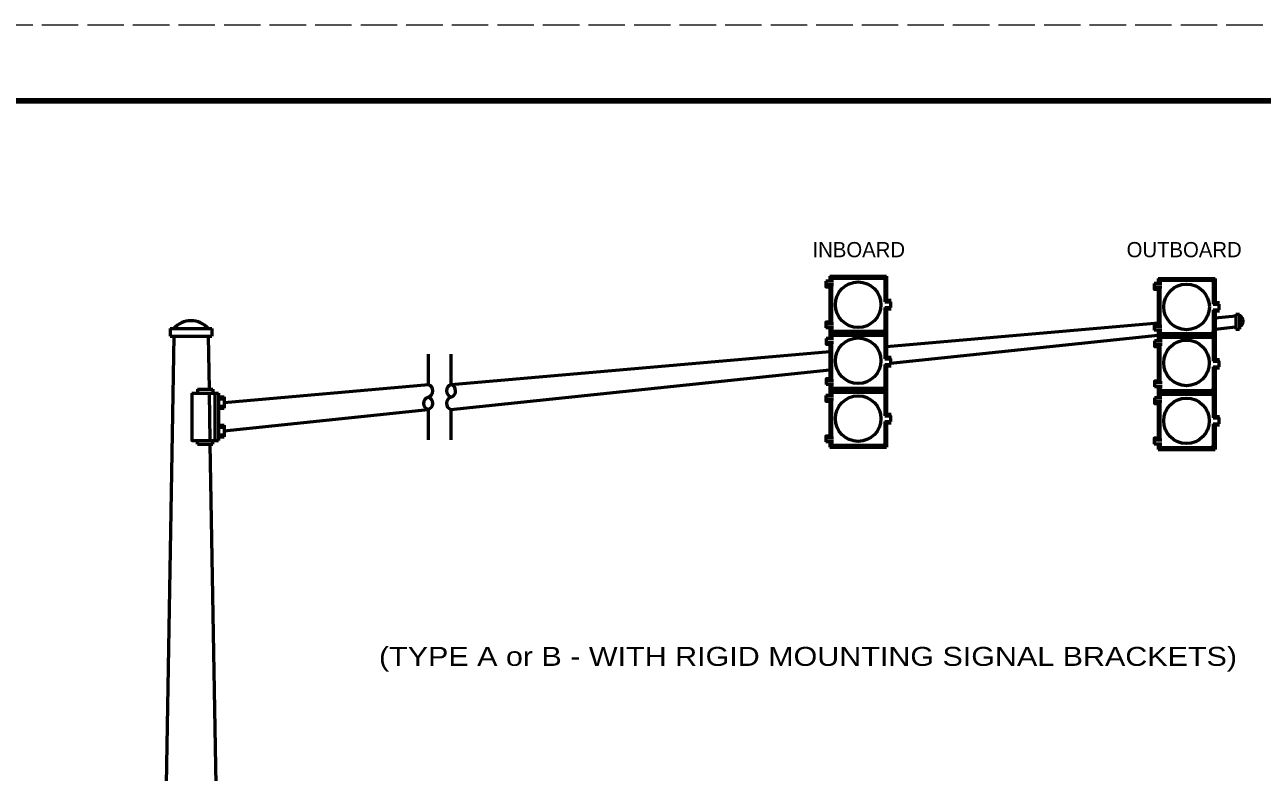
# Model space of a CAD drawing. Extents: x -286 to 394, y -156 to 284.
# Drawn here: x -36.6 to 126.4, y 186.1 to 284.5 of the extents above; entities that cross this region are included whole.
import ezdxf
from ezdxf.enums import TextEntityAlignment as Align

# ---------------------------------------------------------------- set-up
doc = ezdxf.new("R2010")
doc.units = 0
doc.header["$LTSCALE"] = 0.8
doc.linetypes.add('LONG_DASHED', pattern=[7.5, 6, -1.5])
doc.layers.add('1', color=7, linetype='Continuous', lineweight=53)
doc.layers.add('61', color=7, linetype='Continuous', lineweight=35)

msp = doc.modelspace()

# ---------------------------------------------------------------- linework, layer by layer
at = {"layer": '1'}
for p, q in [((69.4161, 251.3764), (76.9161, 251.3764)), ((69.4161, 251.3764), (69.4161, 250.7164)), ((69.9161, 251.1264), (76.4161, 251.1264)), ((76.9161, 251.3764), (76.9161, 248.0014)), ((112.6687, 251.0868), (120.1687, 251.0868)), ((112.6687, 251.0868), (112.6687, 250.4268)), ((120.1687, 251.0868), (120.1687, 247.7118)), ((69.9161, 250.7164), (68.9161, 250.7164)), ((69.9161, 250.2164), (68.9161, 250.2164)), ((69.4161, 250.2164), (69.4161, 245.056)), ((69.6661, 250.8764), (69.6661, 250.7164)), ((69.6661, 250.2164), (69.6661, 245.056)), ((76.6661, 250.8764), (76.6661, 248.0014)), ((113.1687, 250.4268), (112.1687, 250.4268)), ((113.1687, 249.9268), (112.1687, 249.9268)), ((112.6687, 249.9268), (112.6687, 244.7664)), ((112.9187, 250.5868), (112.9187, 250.4268)), ((112.9187, 249.9268), (112.9187, 244.7664)), ((113.1687, 250.8368), (119.6687, 250.8368)), ((119.9187, 250.5868), (119.9187, 247.7118)), ((76.6661, 248.0014), (77.4161, 248.0014)), ((77.2911, 248.3764), (77.2911, 248.0014)), ((77.4161, 248.0014), (77.4161, 247.2514)), ((120.5437, 248.0868), (120.5437, 247.7118)), ((76.6661, 247.2514), (76.6661, 244.3764)), ((76.6661, 247.2514), (77.4161, 247.2514)), ((76.9161, 247.2514), (76.9161, 240.5014)), ((77.2911, 247.2514), (77.2911, 246.8764)), ((119.9187, 247.7118), (120.6687, 247.7118)), ((119.9187, 246.9618), (119.9187, 244.0868)), ((119.9187, 246.9618), (120.6687, 246.9618)), ((120.1687, 246.9618), (120.1687, 240.2118)), ((120.1687, 245.9052), (122.9091, 246.1449)), ((120.5437, 246.9618), (120.5437, 246.5868)), ((120.6687, 247.7118), (120.6687, 246.9618)), ((122.9097, 246.3725), (122.9041, 244.4116)), ((122.9097, 246.3725), (123.4097, 246.3711)), ((123.4097, 246.3711), (123.4041, 244.4102)), ((-17.4518, 244.4995), (-11.9517, 244.4995)), ((-17.4518, 244.4995), (-17.4518, 243.4995)), ((-11.9517, 244.4995), (-11.9517, 243.4995)), ((69.9161, 245.056), (68.9161, 245.056)), ((69.9161, 244.556), (68.9161, 244.556)), ((69.4161, 244.556), (69.4161, 243.1619)), ((69.6661, 244.556), (69.6661, 244.3764)), ((76.9161, 242.1211), (112.6687, 245.249)), ((113.1687, 244.7664), (112.1687, 244.7664)), ((120.1687, 244.4009), (122.9049, 244.6885)), ((-16.9518, 243.4995), (-18.8017, 137.5157)), ((-17.4518, 243.4995), (-11.9517, 243.4995)), ((-12.4518, 243.4995), (-12.3297, 236.5006)), ((69.9369, 243.1619), (68.9369, 243.1619)), ((69.4161, 243.8764), (76.9161, 243.8764)), ((69.6661, 243.3764), (69.6661, 243.1619)), ((69.9161, 244.1264), (76.4161, 244.1264)), ((69.9161, 243.6264), (76.4161, 243.6264)), ((76.6661, 243.3764), (76.6661, 240.5014)), ((77.4161, 239.9077), (112.6687, 243.6128)), ((113.1687, 244.2664), (112.1687, 244.2664)), ((113.1895, 242.8723), (112.1895, 242.8723)), ((112.6687, 244.2664), (112.6687, 242.8723)), ((112.6687, 243.5868), (120.1687, 243.5868)), ((112.9187, 244.2664), (112.9187, 244.0868)), ((112.9187, 243.0868), (112.9187, 242.8723)), ((113.1687, 243.8368), (119.6687, 243.8368)), ((113.1687, 243.3368), (119.6687, 243.3368)), ((119.9187, 243.0868), (119.9187, 240.2118)), ((122.9041, 244.4117), (123.4041, 244.4102)), ((19.5676, 237.1037), (69.4161, 241.4649)), ((69.9369, 242.6619), (68.9369, 242.6619)), ((69.4161, 242.6619), (69.4161, 237.6124)), ((69.6661, 242.6619), (69.6661, 237.6124)), ((113.1895, 242.3723), (112.1895, 242.3723)), ((112.6687, 242.3723), (112.6687, 237.3228)), ((112.9187, 242.3723), (112.9187, 237.3228)), ((16.5676, 237.1037), (16.5676, 241.1037)), ((19.5676, 237.1037), (19.5676, 241.1037)), ((76.6661, 239.7514), (77.4161, 239.7514)), ((76.6661, 239.7514), (76.6661, 236.8764)), ((76.9161, 239.7514), (76.9161, 233.0014)), ((77.2911, 240.8764), (77.2911, 240.5014)), ((77.2911, 239.7514), (77.2911, 239.3764)), ((120.5437, 240.5868), (120.5437, 240.2118)), ((19.5224, 233.8228), (69.4161, 239.0667)), ((119.9187, 239.4618), (120.6687, 239.4618)), ((119.9187, 239.4618), (119.9187, 236.5868)), ((120.1687, 239.4618), (120.1687, 232.7118)), ((120.5437, 239.4618), (120.5437, 239.0868)), ((-13.8297, 236.5006), (-11.8297, 236.5006)), ((-13.8297, 236.5006), (-13.8297, 236.0006)), ((-11.8297, 236.5006), (-11.8297, 236.0006)), ((-10.3297, 234.7506), (16.5676, 237.1037)), ((69.9369, 237.6124), (68.9369, 237.6124)), ((69.9369, 237.1124), (68.9369, 237.1124)), ((69.4161, 237.1124), (69.4161, 235.6753)), ((69.4161, 236.3764), (76.9161, 236.3764)), ((69.6661, 237.1124), (69.6661, 236.8764)), ((69.9161, 236.6264), (76.4161, 236.6264)), ((113.1895, 237.3228), (112.1895, 237.3228)), ((113.1895, 236.8228), (112.1895, 236.8228)), ((112.6687, 236.8228), (112.6687, 235.3857)), ((112.9187, 236.8228), (112.9187, 236.5868)), ((113.1687, 236.3368), (119.6687, 236.3368)), ((-14.5797, 236.0006), (-11.0797, 236.0006)), ((-12.3209, 236.0006), (-12.2118, 229.7506)), ((-11.5797, 236.0006), (-11.5797, 229.7506)), ((-11.0797, 236.0006), (-11.0797, 229.7506)), ((-11.0797, 235.5006), (-10.3297, 235.5006)), ((-11.0797, 235.2506), (-10.3297, 235.2506)), ((-10.3297, 235.5006), (-10.3297, 234.0006)), ((69.9286, 235.6753), (68.9286, 235.6753)), ((69.9286, 235.1753), (68.9286, 235.1753)), ((69.4161, 235.1753), (69.4161, 230.0765)), ((69.6661, 235.8764), (69.6661, 235.6753)), ((69.6661, 235.1753), (69.6661, 230.0765)), ((69.9161, 236.1264), (76.4161, 236.1264)), ((76.6661, 235.8764), (76.6661, 233.0014)), ((113.1812, 235.3857), (112.1812, 235.3857)), ((113.1812, 234.8857), (112.1812, 234.8857)), ((112.6687, 236.0868), (120.1687, 236.0868)), ((112.6687, 234.8857), (112.6687, 229.7869)), ((112.9187, 235.5868), (112.9187, 235.3857)), ((112.9187, 234.8857), (112.9187, 229.7869)), ((113.1687, 235.8368), (119.6687, 235.8368)), ((119.9187, 235.5868), (119.9187, 232.7118)), ((-11.0797, 234.2506), (-10.3297, 234.2506)), ((-11.0797, 234.0006), (-10.3297, 234.0006)), ((-10.3297, 231.0006), (16.5224, 233.8228)), ((16.5224, 233.8228), (16.5224, 229.8228)), ((19.5224, 233.8228), (19.5224, 229.8228)), ((77.2911, 233.3764), (77.2911, 233.0014)), ((120.5437, 233.0868), (120.5437, 232.7118)), ((-11.0797, 231.7506), (-10.3297, 231.7506)), ((-11.0797, 231.5006), (-10.3297, 231.5006)), ((-10.3297, 231.7506), (-10.3297, 230.2506)), ((76.6661, 232.2514), (77.4161, 232.2514)), ((76.6661, 232.2514), (76.6661, 229.3764)), ((76.9161, 232.2514), (76.9161, 228.8764)), ((77.2911, 232.2514), (77.2911, 231.8764)), ((119.9187, 231.9618), (120.6687, 231.9618)), ((119.9187, 231.9618), (119.9187, 229.0868)), ((120.1687, 231.9618), (120.1687, 228.5868)), ((120.5437, 231.9618), (120.5437, 231.5868)), ((-11.0797, 230.5006), (-10.3297, 230.5006)), ((-11.0797, 230.2506), (-10.3297, 230.2506)), ((69.9154, 230.0765), (68.9154, 230.0765)), ((-13.8297, 229.2506), (-13.8297, 229.7506)), ((-13.8297, 229.2506), (-11.8297, 229.2506)), ((-12.2031, 229.2506), (-10.6018, 137.5157)), ((-11.8297, 229.2506), (-11.8297, 229.7506)), ((69.9154, 229.5765), (68.9154, 229.5765)), ((69.4161, 229.5765), (69.4161, 228.8764)), ((69.4161, 228.8764), (76.9161, 228.8764)), ((69.6661, 229.5765), (69.6661, 229.3764)), ((69.9161, 229.1264), (76.4161, 229.1264)), ((113.168, 229.7869), (112.168, 229.7869)), ((113.168, 229.2869), (112.168, 229.2869)), ((112.6687, 229.2869), (112.6687, 228.5868)), ((112.6687, 228.5868), (120.1687, 228.5868)), ((112.9187, 229.2869), (112.9187, 229.0868)), ((113.1687, 228.8368), (119.6687, 228.8368))]:
    msp.add_line(p, q, dxfattribs=at)
for points in [[(68.9161, 250.7164), (68.9161, 249.9664), (69.4161, 249.9664)], [(112.1687, 250.4268), (112.1687, 249.6768), (112.6687, 249.6768)], [(69.4161, 245.306), (68.9161, 245.306), (68.9161, 244.556)], [(112.6687, 245.0164), (112.1687, 245.0164), (112.1687, 244.2664)], [(68.9369, 243.1619), (68.9369, 242.4119), (69.4161, 242.4119)], [(112.1895, 242.8723), (112.1895, 242.1223), (112.6687, 242.1223)], [(76.6661, 240.5014), (77.4161, 240.5014), (77.4161, 239.7514)], [(119.9187, 240.2118), (120.6687, 240.2118), (120.6687, 239.4618)], [(69.4369, 237.8624), (68.9369, 237.8624), (68.9369, 237.1124)], [(112.6895, 237.5728), (112.1895, 237.5728), (112.1895, 236.8228)], [(-14.5797, 236.0006), (-14.5797, 229.7506), (-11.0797, 229.7506)], [(68.9286, 235.6753), (68.9286, 234.9253), (69.4286, 234.9253)], [(112.1812, 235.3857), (112.1812, 234.6357), (112.6812, 234.6357)], [(76.6661, 233.0014), (77.4161, 233.0014), (77.4161, 232.2514)], [(119.9187, 232.7118), (120.6687, 232.7118), (120.6687, 231.9618)], [(69.4154, 230.3265), (68.9154, 230.3265), (68.9154, 229.5765)], [(112.668, 230.0369), (112.168, 230.0369), (112.168, 229.2869)]]:
    msp.add_lwpolyline(points, dxfattribs=at)
for centre in [(73.1692, 247.6235), (116.4218, 247.3339), (73.1635, 240.2517), (116.4161, 239.9621), (73.1633, 232.6276), (116.4159, 232.338)]:
    msp.add_circle(centre, 3, dxfattribs=at)
for centre, radius, start, end in [((69.9161, 250.8765), 0.25, 90, 180), ((76.4161, 250.8765), 0.25, 0, 90), ((113.1687, 250.5869), 0.25, 90, 180), ((119.6687, 250.5869), 0.25, 0, 90), ((123.059, 245.4659), 0.8032, 295.52475, 64.15201), ((-14.7017, 242.4682), 3.0312, 42.07502, 137.92498), ((69.9161, 244.3765), 0.25, 180, 270), ((69.9161, 243.3765), 0.25, 90, 180), ((76.4161, 244.3765), 0.25, 270, 0), ((76.4161, 243.3765), 0.25, 0, 90), ((113.1687, 244.0869), 0.25, 180, 270), ((113.1687, 243.0869), 0.25, 90, 180), ((119.6687, 244.0869), 0.25, 270, 0), ((119.6687, 243.0869), 0.25, 0, 90), ((16.2948, 236.2871), 0.861, 286.89464, 71.52798), ((19.8178, 236.28), 0.861, 106.89464, 251.52798), ((19.2955, 236.28), 0.861, 288.47202, 73.10536), ((69.9161, 236.8765), 0.25, 180, 270), ((76.4161, 236.8765), 0.25, 270, 0), ((113.1687, 236.5869), 0.25, 180, 270), ((119.6687, 236.5869), 0.25, 270, 0), ((16.7945, 234.6466), 0.861, 108.47202, 253.10536), ((16.2722, 234.6466), 0.861, 286.89464, 71.52798), ((19.7952, 234.6395), 0.861, 106.89464, 251.52798), ((69.9161, 235.8765), 0.25, 90, 180), ((76.4161, 235.8765), 0.25, 0, 90), ((113.1687, 235.5869), 0.25, 90, 180), ((119.6687, 235.5869), 0.25, 0, 90), ((69.9161, 229.3765), 0.25, 180, 270), ((76.4161, 229.3765), 0.25, 270, 0), ((113.1687, 229.0869), 0.25, 180, 270), ((119.6687, 229.0869), 0.25, 270, 0)]:
    msp.add_arc(centre, radius, start, end, dxfattribs=at)
at = {"layer": '61', "linetype": 'LONG_DASHED', "lineweight": 13}
msp.add_line((-286.3491, 284.4627), (393.6709, 284.4627), dxfattribs=at)
at = {"layer": '61', "lineweight": 158}
msp.add_lwpolyline([(382.6909, 274.4627), (-256.3491, 274.4627), (-256.3491, -145.5572)], dxfattribs=at)

# ---------------------------------------------------------------- texts
at = {"layer": '1'}
for s, p in [('INBOARD', (73.2492, 253.8691)), ('OUTBOARD', (116.1035, 253.8691))]:
    msp.add_text(s, height=2, dxfattribs=at).set_placement(p, align=Align.CENTER)
at = {"layer": '1', "width": 1.2}
msp.add_text('(TYPE A or B - WITH RIGID MOUNTING SIGNAL BRACKETS)', height=2.5, dxfattribs=at).set_placement((66.5597, 200.086), align=Align.CENTER)

doc.saveas('drawing.dxf')
